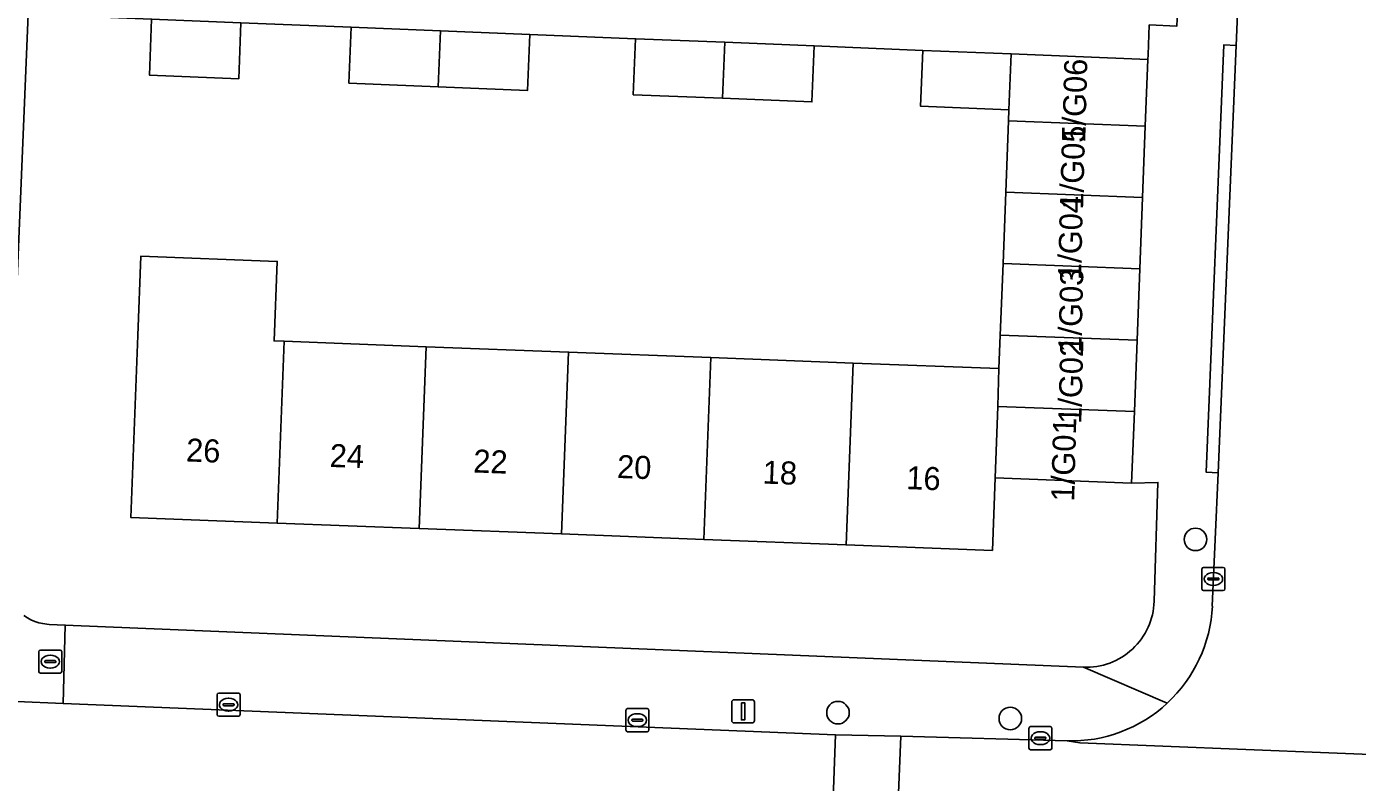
# Model space of a CAD drawing. Extents: x 161354 to 162026, y 386504 to 387460.
# Drawn here: x 161675.2 to 161732.9, y 386647.1 to 386679.9 of the extents above; entities that cross this region are included whole.
import ezdxf

# ---------------------------------------------------------------- set-up
doc = ezdxf.new("R2010")
doc.units = 0
for name, color, linetype in [('IMGEO_Boom', 7, 'Continuous'), ('IMGEO_Brandkraan', 7, 'Continuous'), ('IMGEO_Erf', 7, 'Continuous'), ('IMGEO_Kolk', 7, 'Continuous'), ('IMGEO_Lichtmast', 7, 'Continuous'), ('IMGEO_Pand', 7, 'Continuous'), ('IMGEO_Pand_nummerreeks', 7, 'Continuous'), ('IMGEO_Rijbaan_lokaal_open', 7, 'Continuous'), ('IMGEO_Voetpad_open', 7, 'Continuous')]:
    doc.layers.add(name, color=color, linetype=linetype)

msp = doc.modelspace()

# ---------------------------------------------------------------- linework, layer by layer
at = {"layer": 'IMGEO_Boom'}
for centre in [(161725.893, 386657.6), (161710.377, 386650.081), (161717.855, 386649.828)]:
    msp.add_circle(centre, 0.489, dxfattribs=at)
at = {"layer": 'IMGEO_Brandkraan'}
for p, q in [((161675.697, 386651.869), (161675.697, 386652.721)), ((161675.772, 386652.795), (161676.624, 386652.795)), ((161676.185, 386652.575), (161676.21, 386652.575)), ((161676.698, 386652.721), (161676.698, 386651.869)), ((161675.956, 386652.289), (161675.956, 386652.301)), ((161676.394, 386652.252), (161675.996, 386652.252)), ((161675.999, 386652.338), (161676.397, 386652.338)), ((161676.208, 386652.015), (161676.183, 386652.015)), ((161676.44, 386652.301), (161676.44, 386652.289)), ((161676.624, 386651.795), (161675.772, 386651.795))]:
    msp.add_line(p, q, dxfattribs=at)
for points in [[(161675.697, 386651.869), (161675.697, 386652.721)], [(161675.772, 386652.795), (161676.624, 386652.795)], [(161676.698, 386652.721), (161676.698, 386651.869)], [(161676.624, 386651.795), (161675.772, 386651.795)]]:
    msp.add_lwpolyline(points, dxfattribs=at)
for centre, radius, start, end in [((161675.774, 386652.719), 0.0765, 91.55205, 178.44795), ((161675.774, 386652.719), 0.0765, 91.55205, 178.44795), ((161676.622, 386652.719), 0.0765, 1.55205, 88.44795), ((161676.622, 386652.719), 0.0765, 1.55205, 88.44795), ((161675.774, 386651.871), 0.0765, 181.55205, 268.44795), ((161675.774, 386651.871), 0.0765, 181.55205, 268.44795), ((161675.996, 386652.298), 0.0403, 85.87752, 175.75265), ((161675.993, 386652.288), 0.0366, 178.93798, 274.71019), ((161676.397, 386652.295), 0.043, 264.86636, 352.45326), ((161676.401, 386652.3), 0.0386, 1.73085, 96.63898), ((161676.622, 386651.871), 0.0765, 271.55205, 358.44795), ((161676.622, 386651.871), 0.0765, 271.55205, 358.44795)]:
    msp.add_arc(centre, radius, start, end, dxfattribs=at)
for centre, major_axis, ratio, start_param, end_param in [((161676.184, 386652.295), (-0.387, 0.002), 0.722429, 4.712389, 7.853982), ((161676.209, 386652.295), (-0.39, 0.002), 0.717154, 1.570796, 4.712389)]:
    msp.add_ellipse(centre, major_axis=major_axis, ratio=ratio, start_param=start_param, end_param=end_param, dxfattribs=at)
at = {"layer": 'IMGEO_Erf'}
for points in [[(161717.42, 386666.469), (161717.539, 386669.567), (161717.658, 386672.664), (161717.777, 386675.762), (161717.795, 386676.239), (161713.961, 386676.394), (161714.059, 386678.822), (161709.346, 386679.013), (161709.247, 386676.585), (161705.371, 386676.742), (161701.494, 386676.898), (161701.592, 386679.326), (161697.01, 386679.512), (161696.912, 386677.084), (161693.035, 386677.241), (161689.158, 386677.398), (161689.257, 386679.826), (161684.47, 386680.019), (161684.372, 386677.591), (161680.495, 386677.748), (161680.594, 386680.176), (161675.236, 386680.393), (161674.229, 386655.994)], [(161724.096, 386654.913), (161724.259, 386660.073), (161723.12, 386660.046), (161717.202, 386660.273), (161717.081, 386657.119), (161710.731, 386657.363), (161704.558, 386657.6), (161698.385, 386657.836), (161692.211, 386658.073), (161686.038, 386658.31), (161679.688, 386658.554), (161679.991, 386666.443), (161680.123, 386669.889), (161686.044, 386669.661), (161685.911, 386666.216), (161686.341, 386666.199), (161692.514, 386665.962), (161698.688, 386665.725), (161704.861, 386665.489), (161711.034, 386665.252), (161717.364, 386665.01), (161717.42, 386666.469)], [(161675.052, 386654.292), (161675.201, 386654.194), (161675.359, 386654.109), (161675.523, 386654.038), (161675.693, 386653.983), (161675.868, 386653.943), (161676.045, 386653.919), (161676.142, 386653.912), (161676.845, 386653.881), (161721.025, 386652.051)]]:
    msp.add_lwpolyline(points, dxfattribs=at)
msp.add_arc((161721.139, 386655.007), 2.959, 267.7935, 358.17149, dxfattribs=at)
at = {"layer": 'IMGEO_Kolk'}
for p, q in [((161726.168, 386655.455), (161726.168, 386656.307)), ((161726.243, 386656.381), (161727.095, 386656.381)), ((161726.427, 386655.875), (161726.427, 386655.887)), ((161726.47, 386655.924), (161726.868, 386655.924)), ((161726.656, 386656.161), (161726.681, 386656.161)), ((161726.911, 386655.887), (161726.911, 386655.875)), ((161727.169, 386656.307), (161727.169, 386655.455)), ((161727.095, 386655.381), (161726.243, 386655.381)), ((161726.865, 386655.838), (161726.467, 386655.838)), ((161726.679, 386655.601), (161726.654, 386655.601)), ((161683.434, 386650.001), (161683.434, 386650.853)), ((161683.509, 386650.927), (161684.361, 386650.927)), ((161683.922, 386650.707), (161683.947, 386650.707)), ((161684.435, 386650.853), (161684.435, 386650.001)), ((161683.693, 386650.421), (161683.693, 386650.433)), ((161684.131, 386650.384), (161683.733, 386650.384)), ((161683.736, 386650.47), (161684.134, 386650.47)), ((161683.945, 386650.147), (161683.92, 386650.147)), ((161684.177, 386650.433), (161684.177, 386650.421)), ((161701.171, 386649.329), (161701.171, 386650.181)), ((161701.246, 386650.255), (161702.098, 386650.255)), ((161702.172, 386650.181), (161702.172, 386649.329)), ((161684.361, 386649.927), (161683.509, 386649.927)), ((161701.43, 386649.749), (161701.43, 386649.761)), ((161701.868, 386649.712), (161701.47, 386649.712)), ((161701.473, 386649.798), (161701.871, 386649.798)), ((161701.659, 386650.035), (161701.684, 386650.035)), ((161701.914, 386649.761), (161701.914, 386649.749)), ((161702.098, 386649.255), (161701.246, 386649.255)), ((161701.682, 386649.475), (161701.657, 386649.475)), ((161718.662, 386648.547), (161718.662, 386649.399)), ((161718.737, 386649.473), (161719.589, 386649.473)), ((161718.921, 386648.967), (161718.921, 386648.979)), ((161718.964, 386649.016), (161719.362, 386649.016)), ((161719.15, 386649.253), (161719.175, 386649.253)), ((161719.405, 386648.979), (161719.405, 386648.967)), ((161719.663, 386649.399), (161719.663, 386648.547)), ((161719.589, 386648.473), (161718.737, 386648.473)), ((161719.359, 386648.93), (161718.961, 386648.93)), ((161719.173, 386648.693), (161719.148, 386648.693))]:
    msp.add_line(p, q, dxfattribs=at)
for points in [[(161726.168, 386655.455), (161726.168, 386656.307)], [(161726.243, 386656.381), (161727.095, 386656.381)], [(161727.169, 386656.307), (161727.169, 386655.455)], [(161727.095, 386655.381), (161726.243, 386655.381)], [(161683.434, 386650.001), (161683.434, 386650.853)], [(161683.509, 386650.927), (161684.361, 386650.927)], [(161684.435, 386650.853), (161684.435, 386650.001)], [(161701.171, 386649.329), (161701.171, 386650.181)], [(161701.246, 386650.255), (161702.098, 386650.255)], [(161702.172, 386650.181), (161702.172, 386649.329)], [(161684.361, 386649.927), (161683.509, 386649.927)], [(161702.098, 386649.255), (161701.246, 386649.255)], [(161718.662, 386648.547), (161718.662, 386649.399)], [(161718.737, 386649.473), (161719.589, 386649.473)], [(161719.663, 386649.399), (161719.663, 386648.547)], [(161719.589, 386648.473), (161718.737, 386648.473)]]:
    msp.add_lwpolyline(points, dxfattribs=at)
for centre, radius, start, end in [((161726.245, 386656.305), 0.0765, 91.55205, 178.44795), ((161726.245, 386656.305), 0.0765, 91.55205, 178.44795), ((161726.467, 386655.884), 0.0403, 85.87752, 175.75265), ((161726.464, 386655.874), 0.0366, 178.93798, 274.71019), ((161726.868, 386655.881), 0.043, 264.86636, 352.45326), ((161726.872, 386655.886), 0.0386, 1.73085, 96.63898), ((161727.093, 386656.305), 0.0765, 1.55205, 88.44795), ((161727.093, 386656.305), 0.0765, 1.55205, 88.44795), ((161726.245, 386655.457), 0.0765, 181.55205, 268.44795), ((161726.245, 386655.457), 0.0765, 181.55205, 268.44795), ((161727.093, 386655.457), 0.0765, 271.55205, 358.44795), ((161727.093, 386655.457), 0.0765, 271.55205, 358.44795), ((161683.511, 386650.851), 0.0765, 91.55205, 178.44795), ((161683.511, 386650.851), 0.0765, 91.55205, 178.44795), ((161684.359, 386650.851), 0.0765, 1.55205, 88.44795), ((161684.359, 386650.851), 0.0765, 1.55205, 88.44795), ((161683.733, 386650.43), 0.0403, 85.87752, 175.75265), ((161683.73, 386650.42), 0.0366, 178.93798, 274.71019), ((161684.134, 386650.427), 0.043, 264.86636, 352.45326), ((161684.138, 386650.432), 0.0386, 1.73085, 96.63898), ((161701.248, 386650.179), 0.0765, 91.55205, 178.44795), ((161701.248, 386650.179), 0.0765, 91.55205, 178.44795), ((161702.096, 386650.179), 0.0765, 1.55205, 88.44795), ((161702.096, 386650.179), 0.0765, 1.55205, 88.44795), ((161683.511, 386650.003), 0.0765, 181.55205, 268.44795), ((161683.511, 386650.003), 0.0765, 181.55205, 268.44795), ((161684.359, 386650.003), 0.0765, 271.55205, 358.44795), ((161684.359, 386650.003), 0.0765, 271.55205, 358.44795), ((161701.47, 386649.758), 0.0403, 85.87752, 175.75265), ((161701.467, 386649.748), 0.0366, 178.93798, 274.71019), ((161701.871, 386649.755), 0.043, 264.86636, 352.45326), ((161701.875, 386649.76), 0.0386, 1.73085, 96.63898), ((161701.248, 386649.331), 0.0765, 181.55205, 268.44795), ((161701.248, 386649.331), 0.0765, 181.55205, 268.44795), ((161702.096, 386649.331), 0.0765, 271.55205, 358.44795), ((161702.096, 386649.331), 0.0765, 271.55205, 358.44795), ((161718.739, 386649.397), 0.0765, 91.55205, 178.44795), ((161718.739, 386649.397), 0.0765, 91.55205, 178.44795), ((161718.961, 386648.976), 0.0403, 85.87752, 175.75265), ((161718.958, 386648.966), 0.0366, 178.93798, 274.71019), ((161719.362, 386648.973), 0.043, 264.86636, 352.45326), ((161719.366, 386648.978), 0.0386, 1.73085, 96.63898), ((161719.587, 386649.397), 0.0765, 1.55205, 88.44795), ((161719.587, 386649.397), 0.0765, 1.55205, 88.44795), ((161718.739, 386648.549), 0.0765, 181.55205, 268.44795), ((161718.739, 386648.549), 0.0765, 181.55205, 268.44795), ((161719.587, 386648.549), 0.0765, 271.55205, 358.44795), ((161719.587, 386648.549), 0.0765, 271.55205, 358.44795)]:
    msp.add_arc(centre, radius, start, end, dxfattribs=at)
for centre, major_axis, ratio, start_param, end_param in [((161726.655, 386655.881), (-0.387, 0.002), 0.722429, 4.712389, 7.853982), ((161726.68, 386655.881), (-0.39, 0.002), 0.717154, 1.570796, 4.712389), ((161683.921, 386650.427), (-0.387, 0.002), 0.722429, 4.712389, 7.853982), ((161683.946, 386650.427), (-0.39, 0.002), 0.717154, 1.570796, 4.712389), ((161701.658, 386649.755), (-0.387, 0.002), 0.722429, 4.712389, 7.853982), ((161701.683, 386649.755), (-0.39, 0.002), 0.717154, 1.570796, 4.712389), ((161719.149, 386648.973), (-0.387, 0.002), 0.722429, 4.712389, 7.853982), ((161719.174, 386648.973), (-0.39, 0.002), 0.717154, 1.570796, 4.712389)]:
    msp.add_ellipse(centre, major_axis=major_axis, ratio=ratio, start_param=start_param, end_param=end_param, dxfattribs=at)
at = {"layer": 'IMGEO_Lichtmast'}
for p, q in [((161705.765, 386649.738), (161705.765, 386650.538)), ((161705.765, 386650.538), (161705.765, 386649.738)), ((161705.865, 386650.638), (161706.655, 386650.638)), ((161706.655, 386650.638), (161705.865, 386650.638)), ((161706.755, 386650.538), (161706.755, 386649.738)), ((161706.755, 386649.738), (161706.755, 386650.538)), ((161706.655, 386649.638), (161705.865, 386649.638)), ((161705.865, 386649.638), (161706.655, 386649.638))]:
    msp.add_line(p, q, dxfattribs=at)
msp.add_lwpolyline([(161706.185, 386650.513), (161706.335, 386650.513), (161706.335, 386649.763), (161706.185, 386649.763), (161706.185, 386650.513)], dxfattribs=at)
for centre, start, end in [((161705.865, 386650.538), 90, 180), ((161705.865, 386650.538), 90, 180), ((161706.655, 386650.538), 0, 90), ((161706.655, 386650.538), 360, 90), ((161705.865, 386649.738), 180, 270), ((161705.865, 386649.738), 180, 270), ((161706.655, 386649.738), 270, 0), ((161706.655, 386649.738), 270, 0)]:
    msp.add_arc(centre, 0.1, start, end, dxfattribs=at)
at = {"layer": 'IMGEO_Pand'}
for points in [[(161684.47, 386680.019), (161680.594, 386680.176), (161680.495, 386677.748), (161684.372, 386677.591)], [(161693.133, 386679.669), (161689.257, 386679.826), (161689.158, 386677.398), (161693.035, 386677.241)], [(161697.01, 386679.512), (161693.133, 386679.669), (161693.035, 386677.241), (161696.912, 386677.084)], [(161705.469, 386679.17), (161701.592, 386679.326), (161701.494, 386676.898), (161705.371, 386676.742)], [(161709.346, 386679.013), (161705.469, 386679.17), (161705.371, 386676.742), (161709.247, 386676.585)], [(161717.893, 386678.667), (161714.059, 386678.822), (161713.961, 386676.394), (161717.795, 386676.239)], [(161723.825, 386678.427), (161717.893, 386678.667), (161717.795, 386676.239), (161717.777, 386675.762), (161723.714, 386675.534)], [(161717.777, 386675.762), (161717.658, 386672.664), (161723.595, 386672.437), (161723.714, 386675.534)], [(161717.658, 386672.664), (161717.539, 386669.567), (161723.476, 386669.339), (161723.595, 386672.437)], [(161686.341, 386666.199), (161685.911, 386666.216), (161686.044, 386669.661), (161680.123, 386669.889), (161679.991, 386666.443), (161679.688, 386658.554), (161686.038, 386658.31)], [(161723.358, 386666.241), (161723.476, 386669.339), (161717.539, 386669.567), (161717.42, 386666.469)], [(161717.42, 386666.469), (161717.364, 386665.01), (161717.308, 386663.371), (161723.239, 386663.144), (161723.358, 386666.241)], [(161692.514, 386665.962), (161686.341, 386666.199), (161686.038, 386658.31), (161692.211, 386658.073)], [(161692.211, 386658.073), (161698.385, 386657.836), (161698.688, 386665.725), (161692.514, 386665.962)], [(161704.861, 386665.489), (161698.688, 386665.725), (161698.385, 386657.836), (161704.558, 386657.6)], [(161711.034, 386665.252), (161704.861, 386665.489), (161704.558, 386657.6), (161710.731, 386657.363)], [(161717.308, 386663.371), (161717.364, 386665.01), (161711.034, 386665.252), (161710.731, 386657.363), (161717.081, 386657.119), (161717.202, 386660.273)], [(161723.239, 386663.144), (161717.308, 386663.371), (161717.202, 386660.273), (161723.12, 386660.046)]]:
    msp.add_lwpolyline(points, close=True, dxfattribs=at)
at = {"layer": 'IMGEO_Rijbaan_lokaal_open'}
for points in [[(161674.229, 386655.994), (161675.236, 386680.393), (161675.298, 386681.892), (161676.837, 386719.2), (161676.9, 386720.715), (161677.78, 386742.025)], [(161735.471, 386699.54), (161735.824, 386708.256), (161728.888, 386708.517), (161728.502, 386699.051), (161727.654, 386679.034), (161726.868, 386660.492), (161726.622, 386654.699)], [(161666.695, 386650.908), (161676.751, 386650.485), (161676.845, 386653.881), (161676.142, 386653.912), (161676.045, 386653.919), (161675.868, 386653.943), (161675.693, 386653.983), (161675.523, 386654.038), (161675.359, 386654.109), (161675.201, 386654.194), (161675.052, 386654.292)], [(161720.322, 386648.852), (161720.876, 386648.777), (161738.887, 386648.046)]]:
    msp.add_lwpolyline(points, dxfattribs=at)
for points in [[(161710.274, 386649.125), (161676.751, 386650.485), (161666.695, 386650.908), (161651.334, 386651.513), (161651.06, 386644.589), (161660.892, 386644.188), (161661.129, 386644.197), (161679.181, 386643.378), (161684.097, 386643.288), (161710.025, 386642.456)], [(161713.108, 386649.066), (161710.274, 386649.125), (161710.025, 386642.456), (161712.823, 386642.344)], [(161761.932, 386647.046), (161749.864, 386647.448), (161738.887, 386648.046), (161720.876, 386648.777), (161720.322, 386648.852), (161713.108, 386649.066), (161712.823, 386642.344), (161749.109, 386640.895), (161761.539, 386640.379)]]:
    msp.add_lwpolyline(points, close=True, dxfattribs=at)
for centre, radius, start, end in [((161720.485, 386654.998), 6.145, 312.89482, 357.21477), ((161720.48, 386654.999), 6.149, 268.53118, 312.91869)]:
    msp.add_arc(centre, radius, start, end, dxfattribs=at)
at = {"layer": 'IMGEO_Voetpad_open'}
for points in [[(161725.679, 386725.179), (161725.556, 386722.095), (161725.432, 386719.01), (161725.424, 386718.816), (161726.724, 386718.765), (161726.661, 386717.261), (161725.096, 386680.182), (161725.083, 386679.877), (161723.886, 386679.925), (161723.833, 386678.632), (161723.825, 386678.427), (161723.714, 386675.534), (161723.595, 386672.437), (161723.476, 386669.339), (161723.358, 386666.241), (161723.239, 386663.144), (161723.12, 386660.046), (161724.259, 386660.073), (161724.096, 386654.913)], [(161726.622, 386654.699), (161726.868, 386660.492), (161726.36, 386660.511), (161727.119, 386679.055), (161727.654, 386679.034), (161728.502, 386699.051)], [(161684.47, 386680.019), (161689.257, 386679.826), (161693.133, 386679.669), (161697.01, 386679.512), (161701.592, 386679.326), (161705.469, 386679.17), (161709.346, 386679.013), (161714.059, 386678.822), (161717.893, 386678.667), (161723.825, 386678.427), (161723.833, 386678.632), (161723.886, 386679.925)], [(161721.025, 386652.051), (161676.845, 386653.881), (161676.751, 386650.485), (161710.274, 386649.125), (161713.108, 386649.066), (161720.322, 386648.852)], [(161721.025, 386652.051), (161724.667, 386650.496)], [(161724.667, 386650.496), (161721.025, 386652.051)]]:
    msp.add_lwpolyline(points, dxfattribs=at)
msp.add_lwpolyline([(161727.654, 386679.034), (161727.119, 386679.055), (161726.36, 386660.511), (161726.868, 386660.492)], close=True, dxfattribs=at)
for centre, radius, start, end in [((161721.139, 386655.007), 2.959, 267.7935, 358.17149), ((161720.485, 386654.998), 6.145, 312.89482, 357.21477), ((161720.48, 386654.999), 6.149, 268.53118, 312.91869)]:
    msp.add_arc(centre, radius, start, end, dxfattribs=at)

# ---------------------------------------------------------------- texts
at = {"layer": 'IMGEO_Pand_nummerreeks'}
for s, rotation, p in [('1/G06', 88.52198, (161721.107, 386674.806)), ('1/G05', 88.52036, (161721.013, 386671.906)), ('1/G04', 88.52036, (161720.921, 386668.847)), ('1/G03', 88.52036, (161720.935, 386665.695)), ('1/G02', 88.52036, (161720.935, 386662.603)), ('1/G01', 88.52036, (161720.627, 386659.238)), ('26', 357.79984, (161682.075, 386660.984)), ('24', 357.80229, (161688.307, 386660.745)), ('22', 357.80229, (161694.537, 386660.506)), ('20', 357.80229, (161700.775, 386660.267)), ('18', 357.80229, (161707.098, 386660.024)), ('16', 357.80229, (161713.327, 386659.784))]:
    msp.add_text(s, height=1, rotation=rotation, dxfattribs=at).set_placement(p)

doc.saveas('drawing.dxf')
